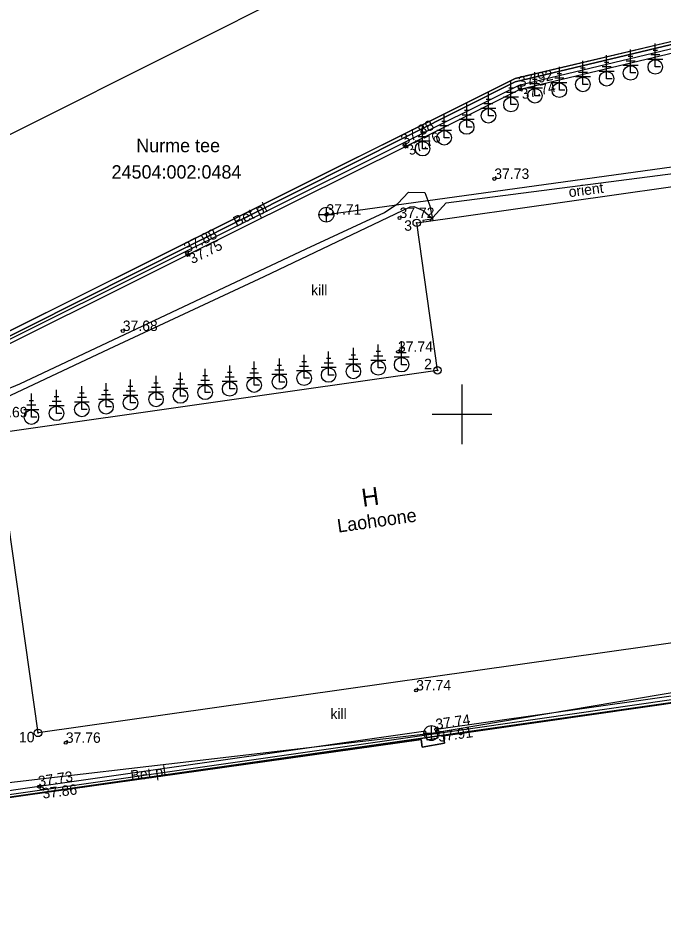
# Model space of a CAD drawing. Extents: x 551828 to 552309, y 6590593 to 6591152.
# Drawn here: x 552070.2 to 552113.5, y 6591016.5 to 6591076.6 of the extents above; entities that cross this region are included whole.
import ezdxf

# ---------------------------------------------------------------- set-up
doc = ezdxf.new("R2010")
doc.units = 0
for name, color, linetype in [('AED', 7, 'Continuous'), ('GTRASS', 7, 'Continuous'), ('HOONE', 7, 'Continuous'), ('KOORDPUNKT', 7, 'Continuous'), ('KORGUS-EH2000', 7, 'Continuous'), ('MOOTPIIR', 7, 'Continuous'), ('MPKAABEL', 7, 'Continuous'), ('PIIR', 7, 'Continuous'), ('PUU', 7, 'Continuous'), ('RAJATIS', 7, 'Continuous'), ('SKKAEV', 7, 'Continuous'), ('SKTRASS', 7, 'Continuous'), ('TEE', 7, 'Continuous'), ('VORK', 7, 'Continuous'), ('VTRASS', 7, 'Continuous')]:
    doc.layers.add(name, color=color, linetype=linetype)

msp = doc.modelspace()

# ---------------------------------------------------------------- linework, layer by layer
at = {"layer": 'AED'}
for points in [[(552147.637, 6591052.26), (552140.304, 6591080.517), (552139.66, 6591082.912), (552137.43, 6591081.846), (552130.717, 6591078.419), (552116.026, 6591074.952), (552103.814, 6591072.044), (552061.896, 6591051.151)], [(552149.845, 6591043.418), (552151.659, 6591036.289), (552099.026, 6591028.695), (552056.657, 6591022.632), (552052.805, 6591046.621), (552057.329, 6591048.844)]]:
    msp.add_lwpolyline(points, dxfattribs=at)
at = {"layer": 'GTRASS'}
msp.add_lwpolyline([(552039.49, 6591041.34), (552039.58, 6591041.38), (552040.12, 6591041.29), (552040.28, 6591041.26), (552040.44, 6591041.25), (552041.72, 6591041.39), (552046.37, 6591043.11), (552053.09, 6591045.39), (552065.47, 6591049.26), (552076.35, 6591054.38), (552086.74, 6591059.24), (552096.54, 6591063.89), (552096.77, 6591063.92), (552097.394, 6591063.649), (552097.933, 6591063.194), (552097.957, 6591063.062), (552097.389, 6591062.977), (552097.402, 6591062.885)], dxfattribs=at)
at = {"layer": 'HOONE'}
msp.add_lwpolyline([(552071.587, 6591028.635), (552068.745, 6591048.736), (552098.36, 6591052.94), (552096.972, 6591062.824), (552117.134, 6591065.69), (552121.395, 6591035.706)], close=True, dxfattribs=at)
at = {"layer": 'KOORDPUNKT'}
for centre, radius in [((552096.972, 6591062.824), 0.25), ((552096.972, 6591062.824), 0.025), ((552096.972, 6591062.824), 0.0221), ((552096.972, 6591062.824), 0.0191), ((552096.972, 6591062.824), 0.0161), ((552096.972, 6591062.824), 0.0132), ((552096.972, 6591062.824), 0.0102), ((552096.972, 6591062.824), 0.00726), ((552096.972, 6591062.824), 0.0043), ((552098.36, 6591052.94), 0.25), ((552098.36, 6591052.94), 0.025), ((552098.36, 6591052.94), 0.0221), ((552098.36, 6591052.94), 0.0191), ((552098.36, 6591052.94), 0.0161), ((552098.36, 6591052.94), 0.0132), ((552098.36, 6591052.94), 0.0102), ((552098.36, 6591052.94), 0.00726), ((552098.36, 6591052.94), 0.0043), ((552071.587, 6591028.635), 0.25), ((552071.587, 6591028.635), 0.025), ((552071.587, 6591028.635), 0.0221), ((552071.587, 6591028.635), 0.0191), ((552071.587, 6591028.635), 0.0161), ((552071.587, 6591028.635), 0.0132), ((552071.587, 6591028.635), 0.0102), ((552071.587, 6591028.635), 0.00726), ((552071.587, 6591028.635), 0.0043)]:
    msp.add_circle(centre, radius, dxfattribs=at)
at = {"layer": 'KORGUS-EH2000'}
for centre in [(552103.866, 6591071.923), (552103.896, 6591071.784), (552096.154, 6591068.028), (552096.222, 6591067.942), (552102.169, 6591065.77), (552090.914, 6591063.376), (552095.815, 6591063.152), (552081.577, 6591060.787), (552081.606, 6591060.679), (552077.267, 6591055.577), (552095.715, 6591054.18), (552096.931, 6591031.481), (552098.285, 6591028.866), (552098.349, 6591028.727), (552073.449, 6591027.971), (552071.652, 6591025.036), (552071.83, 6591024.922)]:
    msp.add_circle(centre, 0.1, dxfattribs=at)
at = {"layer": 'MOOTPIIR'}
msp.add_lwpolyline([(552121.905, 6591031.76), (552098.767, 6591028.437), (552098.829, 6591027.951), (552097.324, 6591027.687), (552097.257, 6591028.201), (552070.742, 6591024.47), (552059.117, 6591022.785), (552056.51, 6591022.407), (552056.403, 6591023.066), (552054.752, 6591033.19), (552052.967, 6591044.185), (552039.584, 6591040.488), (552038.881, 6591041.392), (552037.568, 6591044.196), (552044.191, 6591047.481), (552050.676, 6591050.698), (552057.128, 6591053.914), (552061.407, 6591056.102), (552065.701, 6591058.181), (552066.051, 6591057.524), (552066.981, 6591055.761), (552067.763, 6591054.637), (552103.559, 6591072.502), (552116.628, 6591075.6)], dxfattribs=at)
at = {"layer": 'MPKAABEL'}
msp.add_lwpolyline([(552066.209, 6591053.696), (552066.171, 6591051.167), (552066.803, 6591050.557), (552070.357, 6591052.028), (552089.564, 6591061.079), (552094.799, 6591063.511), (552095.695, 6591064.13), (552096.41, 6591064.875), (552097.511, 6591064.864), (552097.841, 6591063.973), (552098.05, 6591062.977)], dxfattribs=at)
at = {"layer": 'PIIR'}
msp.add_lwpolyline([(551994.68, 6591017.51), (552041.41, 6591041.02), (552052.64, 6591046.67), (552103.56, 6591072.29), (552129.86, 6591078.57), (552139.81, 6591083.25), (552149.14, 6591087.65), (552143.71, 6591108.79), (552138.17, 6591106.07), (552120.12, 6591097.22), (552089.7, 6591078.79), (552070.79, 6591069.29), (552053.16, 6591060.44), (552032.69, 6591050.15), (552014.5, 6591041)], dxfattribs=at)
for points in [[(552052.64, 6591046.67), (552056.49, 6591022.44), (552152.01, 6591036.07), (552139.81, 6591083.25), (552129.86, 6591078.57), (552103.56, 6591072.29)], [(552056.49, 6591022.44), (552064.25, 6590973.06), (552164.61, 6590987.36), (552152.01, 6591036.07)]]:
    msp.add_lwpolyline(points, close=True, dxfattribs=at)
at = {"layer": 'PUU'}
for p, q in [((552112.957, 6591073.279), (552112.957, 6591074.854)), ((552109.698, 6591072.483), (552109.698, 6591074.058)), ((552111.451, 6591073.974), (552111.151, 6591073.974)), ((552111.301, 6591072.874), (552111.301, 6591074.449)), ((552113.257, 6591074.079), (552112.657, 6591074.079)), ((552113.107, 6591074.379), (552112.807, 6591074.379)), ((552106.528, 6591071.715), (552106.528, 6591073.29)), ((552108.106, 6591072.105), (552108.106, 6591073.68)), ((552109.998, 6591073.283), (552109.398, 6591073.283)), ((552109.848, 6591073.583), (552109.548, 6591073.583)), ((552111.801, 6591073.374), (552110.801, 6591073.374)), ((552111.601, 6591073.674), (552111.001, 6591073.674)), ((552113.457, 6591073.779), (552112.457, 6591073.779)), ((552113.317, 6591073.279), (552112.957, 6591073.279)), ((552104.889, 6591071.345), (552104.889, 6591072.92)), ((552106.678, 6591072.815), (552106.378, 6591072.815)), ((552108.406, 6591072.905), (552107.806, 6591072.905)), ((552108.256, 6591073.205), (552107.956, 6591073.205)), ((552110.198, 6591072.983), (552109.198, 6591072.983)), ((552111.661, 6591072.874), (552111.301, 6591072.874)), ((552103.286, 6591070.756), (552103.286, 6591072.331)), ((552105.189, 6591072.145), (552104.589, 6591072.145)), ((552105.039, 6591072.445), (552104.739, 6591072.445)), ((552107.028, 6591072.215), (552106.028, 6591072.215)), ((552106.828, 6591072.515), (552106.228, 6591072.515)), ((552108.606, 6591072.605), (552107.606, 6591072.605)), ((552108.466, 6591072.105), (552108.106, 6591072.105)), ((552110.058, 6591072.483), (552109.698, 6591072.483)), ((552101.777, 6591070.002), (552101.777, 6591071.577)), ((552103.586, 6591071.556), (552102.986, 6591071.556)), ((552103.436, 6591071.856), (552103.136, 6591071.856)), ((552105.389, 6591071.845), (552104.389, 6591071.845)), ((552106.888, 6591071.715), (552106.528, 6591071.715)), ((552101.927, 6591071.102), (552101.627, 6591071.102)), ((552103.786, 6591071.256), (552102.786, 6591071.256)), ((552105.249, 6591071.345), (552104.889, 6591071.345)), ((552100.467, 6591070.349), (552100.167, 6591070.349)), ((552100.317, 6591069.249), (552100.317, 6591070.824)), ((552102.277, 6591070.502), (552101.277, 6591070.502)), ((552102.077, 6591070.802), (552101.477, 6591070.802)), ((552103.646, 6591070.756), (552103.286, 6591070.756)), ((552098.81, 6591068.527), (552098.81, 6591070.102)), ((552100.817, 6591069.749), (552099.817, 6591069.749)), ((552100.617, 6591070.049), (552100.017, 6591070.049)), ((552102.137, 6591070.002), (552101.777, 6591070.002)), ((552097.364, 6591067.794), (552097.364, 6591069.369)), ((552099.11, 6591069.327), (552098.51, 6591069.327)), ((552098.96, 6591069.627), (552098.66, 6591069.627)), ((552100.677, 6591069.249), (552100.317, 6591069.249)), ((552097.664, 6591068.594), (552097.064, 6591068.594)), ((552097.514, 6591068.894), (552097.214, 6591068.894)), ((552099.31, 6591069.027), (552098.31, 6591069.027)), ((552099.17, 6591068.527), (552098.81, 6591068.527)), ((552097.864, 6591068.294), (552096.864, 6591068.294)), ((552097.724, 6591067.794), (552097.364, 6591067.794)), ((552094.392, 6591053.1), (552094.392, 6591054.675)), ((552095.955, 6591053.315), (552095.955, 6591054.89)), ((552091.065, 6591052.623), (552091.065, 6591054.198)), ((552092.723, 6591052.862), (552092.723, 6591054.437)), ((552094.542, 6591054.2), (552094.242, 6591054.2)), ((552096.255, 6591054.115), (552095.655, 6591054.115)), ((552096.105, 6591054.415), (552095.805, 6591054.415)), ((552086.073, 6591051.946), (552086.073, 6591053.521)), ((552087.763, 6591052.157), (552087.763, 6591053.732)), ((552089.57, 6591053.507), (552089.27, 6591053.507)), ((552089.42, 6591052.407), (552089.42, 6591053.982)), ((552091.215, 6591053.723), (552090.915, 6591053.723)), ((552093.023, 6591053.662), (552092.423, 6591053.662)), ((552092.873, 6591053.962), (552092.573, 6591053.962)), ((552094.892, 6591053.6), (552093.892, 6591053.6)), ((552094.692, 6591053.9), (552094.092, 6591053.9)), ((552096.455, 6591053.815), (552095.455, 6591053.815)), ((552082.789, 6591051.464), (552082.789, 6591053.039)), ((552084.432, 6591051.69), (552084.432, 6591053.265)), ((552086.223, 6591053.046), (552085.923, 6591053.046)), ((552088.063, 6591052.957), (552087.463, 6591052.957)), ((552087.913, 6591053.257), (552087.613, 6591053.257)), ((552089.92, 6591052.907), (552088.92, 6591052.907)), ((552089.72, 6591053.207), (552089.12, 6591053.207)), ((552091.565, 6591053.123), (552090.565, 6591053.123)), ((552091.365, 6591053.423), (552090.765, 6591053.423)), ((552093.223, 6591053.362), (552092.223, 6591053.362)), ((552093.083, 6591052.862), (552092.723, 6591052.862)), ((552094.752, 6591053.1), (552094.392, 6591053.1)), ((552096.315, 6591053.315), (552095.955, 6591053.315)), ((552077.786, 6591050.752), (552077.786, 6591052.327)), ((552079.497, 6591050.986), (552079.497, 6591052.561)), ((552081.283, 6591052.319), (552080.983, 6591052.319)), ((552081.133, 6591051.219), (552081.133, 6591052.794)), ((552083.089, 6591052.264), (552082.489, 6591052.264)), ((552082.939, 6591052.564), (552082.639, 6591052.564)), ((552084.732, 6591052.49), (552084.132, 6591052.49)), ((552084.582, 6591052.79), (552084.282, 6591052.79)), ((552086.573, 6591052.446), (552085.573, 6591052.446)), ((552086.373, 6591052.746), (552085.773, 6591052.746)), ((552088.263, 6591052.657), (552087.263, 6591052.657)), ((552089.78, 6591052.407), (552089.42, 6591052.407)), ((552091.425, 6591052.623), (552091.065, 6591052.623)), ((552074.524, 6591050.314), (552074.524, 6591051.889)), ((552076.145, 6591050.495), (552076.145, 6591052.07)), ((552077.936, 6591051.852), (552077.636, 6591051.852)), ((552079.797, 6591051.786), (552079.197, 6591051.786)), ((552079.647, 6591052.086), (552079.347, 6591052.086)), ((552081.633, 6591051.719), (552080.633, 6591051.719)), ((552081.433, 6591052.019), (552080.833, 6591052.019)), ((552083.289, 6591051.964), (552082.289, 6591051.964)), ((552084.932, 6591052.19), (552083.932, 6591052.19)), ((552084.792, 6591051.69), (552084.432, 6591051.69)), ((552086.433, 6591051.946), (552086.073, 6591051.946)), ((552088.123, 6591052.157), (552087.763, 6591052.157)), ((552071.142, 6591049.803), (552071.142, 6591051.378)), ((552072.978, 6591051.153), (552072.678, 6591051.153)), ((552072.828, 6591050.053), (552072.828, 6591051.628)), ((552074.824, 6591051.114), (552074.224, 6591051.114)), ((552074.674, 6591051.414), (552074.374, 6591051.414)), ((552076.445, 6591051.295), (552075.845, 6591051.295)), ((552076.295, 6591051.595), (552075.995, 6591051.595)), ((552078.286, 6591051.252), (552077.286, 6591051.252)), ((552078.086, 6591051.552), (552077.486, 6591051.552)), ((552079.997, 6591051.486), (552078.997, 6591051.486)), ((552081.493, 6591051.219), (552081.133, 6591051.219)), ((552083.149, 6591051.464), (552082.789, 6591051.464)), ((552071.442, 6591050.603), (552070.842, 6591050.603)), ((552071.292, 6591050.903), (552070.992, 6591050.903)), ((552073.328, 6591050.553), (552072.328, 6591050.553)), ((552073.128, 6591050.853), (552072.528, 6591050.853)), ((552075.024, 6591050.814), (552074.024, 6591050.814)), ((552076.645, 6591050.995), (552075.645, 6591050.995)), ((552076.505, 6591050.495), (552076.145, 6591050.495)), ((552078.146, 6591050.752), (552077.786, 6591050.752)), ((552079.857, 6591050.986), (552079.497, 6591050.986)), ((552071.642, 6591050.303), (552070.642, 6591050.303)), ((552073.188, 6591050.053), (552072.828, 6591050.053)), ((552074.884, 6591050.314), (552074.524, 6591050.314)), ((552071.502, 6591049.803), (552071.142, 6591049.803))]:
    msp.add_line(p, q, dxfattribs=at)
at = {"layer": 'RAJATIS'}
for centre in [(552111.301, 6591072.874), (552112.957, 6591073.279), (552109.698, 6591072.483), (552106.528, 6591071.715), (552108.106, 6591072.105), (552104.889, 6591071.345), (552103.286, 6591070.756), (552101.777, 6591070.002), (552100.317, 6591069.249), (552098.81, 6591068.527), (552097.364, 6591067.794), (552094.392, 6591053.1), (552095.955, 6591053.315), (552089.42, 6591052.407), (552091.065, 6591052.623), (552092.723, 6591052.862), (552086.073, 6591051.946), (552087.763, 6591052.157), (552081.133, 6591051.219), (552082.789, 6591051.464), (552084.432, 6591051.69), (552077.786, 6591050.752), (552079.497, 6591050.986), (552072.828, 6591050.053), (552074.524, 6591050.314), (552076.145, 6591050.495), (552071.142, 6591049.803)]:
    msp.add_circle(centre, 0.486, dxfattribs=at)
at = {"layer": 'SKKAEV'}
for p, q in [((552090.914, 6591062.876), (552090.914, 6591063.876)), ((552090.414, 6591063.376), (552091.414, 6591063.376)), ((552097.953, 6591028.127), (552097.953, 6591029.127)), ((552097.453, 6591028.627), (552098.453, 6591028.627))]:
    msp.add_line(p, q, dxfattribs=at)
for centre in [(552090.914, 6591063.376), (552097.953, 6591028.627)]:
    msp.add_circle(centre, 0.5, dxfattribs=at)
at = {"layer": 'SKTRASS'}
for p, q in [((552090.914, 6591063.376), (552122.481, 6591067.745)), ((552097.953, 6591028.627), (552127.852, 6591033.656)), ((552059.584, 6591024.147), (552097.953, 6591028.627))]:
    msp.add_line(p, q, dxfattribs=at)
at = {"layer": 'TEE'}
for points in [[(552146.282, 6591054.85), (552147.086, 6591055.056), (552147.828, 6591052.159), (552148.048, 6591052.225), (552148.008, 6591052.359), (552139.991, 6591083.412), (552139.137, 6591083.215), (552130.577, 6591078.919), (552129.697, 6591078.698), (552103.559, 6591072.502), (552061.628, 6591051.575)], [(552122.699, 6591032.327), (552098.285, 6591028.866), (552098.373, 6591028.276), (552097.676, 6591028.158), (552097.572, 6591028.753), (552071.652, 6591025.036), (552056.869, 6591022.928), (552054.95, 6591034.959), (552053.066, 6591046.467), (552056.375, 6591048.099), (552058.06, 6591048.98), (552061.631, 6591050.768), (552062.335, 6591051.103), (552062.864, 6591051.378), (552065.598, 6591052.716), (552081.606, 6591060.679), (552096.222, 6591067.942), (552103.896, 6591071.784), (552116.575, 6591074.794)], [(552057.2, 6591049.342), (552052.503, 6591047.042), (552054.752, 6591033.19), (552056.403, 6591023.066), (552056.51, 6591022.407), (552059.117, 6591022.785), (552070.742, 6591024.47), (552097.257, 6591028.201), (552097.324, 6591027.687), (552098.829, 6591027.951), (552098.767, 6591028.437), (552121.905, 6591031.76), (552151.303, 6591036.057), (552152.101, 6591036.283), (552150.21, 6591043.556)]]:
    msp.add_lwpolyline(points, dxfattribs=at)
at = {"layer": 'VORK'}
for p, q in [((552100, 6591052), (552100, 6591048)), ((552098, 6591050), (552102, 6591050))]:
    msp.add_line(p, q, dxfattribs=at)
at = {"layer": 'VTRASS'}
msp.add_lwpolyline([(552097.831, 6591062.946), (552098.934, 6591064.176), (552122.078, 6591067.157), (552125.621, 6591044.276), (552152.166, 6591038.134)], dxfattribs=at)

# ---------------------------------------------------------------- texts
at = {"layer": 'HOONE'}
for s, height, p in [('H', 1.2, (552093.363, 6591043.786)), ('Laohoone', 0.9, (552091.707, 6591042.056))]:
    msp.add_text(s, height=height, rotation=8.08006, dxfattribs=at).set_placement(p)
at = {"layer": 'KOORDPUNKT'}
for s, p in [('3', (552096.13, 6591062.297)), ('2', (552097.464, 6591053.016)), ('10', (552070.309, 6591028.004))]:
    msp.add_text(s, height=0.7, dxfattribs=at).set_placement(p)
at = {"layer": 'KORGUS-EH2000'}
for s, rotation, p in [('37.92', 12.18425, (552103.866, 6591071.923)), ('37.74', 12.90737, (552104.052, 6591071.101)), ('37.88', 28.90372, (552096.154, 6591068.028)), ('37.76', 26.10839, (552096.53, 6591067.313)), ('37.88', 26.92687, (552081.577, 6591060.787)), ('37.75', 26.3638, (552081.917, 6591060.051)), ('37.74', 8.3185, (552098.285, 6591028.866)), ('37.91', 7.83981, (552098.444, 6591028.033)), ('37.73', 8.79704, (552071.652, 6591025.036)), ('37.86', 7.13359, (552071.917, 6591024.227))]:
    msp.add_text(s, height=0.7, rotation=rotation, dxfattribs=at).set_placement(p)
for s, p in [('37.73', (552102.169, 6591065.77)), ('37.71', (552090.914, 6591063.376)), ('37.72', (552095.815, 6591063.152)), ('37.68', (552077.267, 6591055.577)), ('37.74', (552095.715, 6591054.18)), ('37.69', (552068.539, 6591049.789)), ('37.74', (552096.931, 6591031.481)), ('37.76', (552073.449, 6591027.971))]:
    msp.add_text(s, height=0.7, dxfattribs=at).set_placement(p)
at = {"layer": 'PIIR'}
for s, p in [('Nurme tee', (552078.168, 6591067.56)), ('24504:002:0484', (552076.517, 6591065.789))]:
    msp.add_text(s, height=0.9, dxfattribs=at).set_placement(p)
at = {"layer": 'TEE'}
for rotation, p in [(26.42424, (552084.887, 6591062.544)), (8.00966, (552077.841, 6591025.414))]:
    msp.add_text('Bet pl', height=0.7, rotation=rotation, dxfattribs=at).set_placement(p)
for p in [(552089.889, 6591057.969), (552091.186, 6591029.567)]:
    msp.add_text('kill', height=0.7, dxfattribs=at).set_placement(p)
at = {"layer": 'VTRASS'}
msp.add_text('orient', height=0.7, rotation=7.33887, dxfattribs=at).set_placement((552107.199, 6591064.545))

doc.saveas('drawing.dxf')
